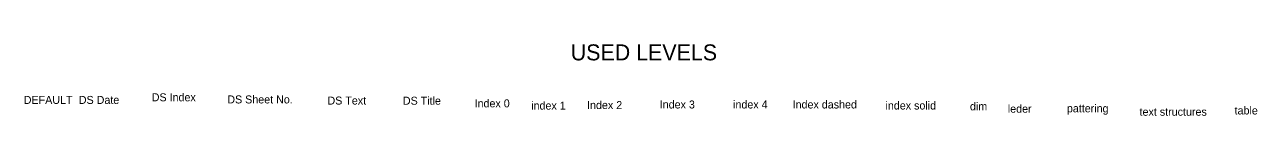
# Model space of a CAD drawing. Extents: x -1.3 to 14.5, y 0 to 8.2.
# Drawn here: x -1.2655 to -1.1115, y -0.0193 to -0.0103 of the extents above; entities that cross this region are included whole.
import ezdxf

# ---------------------------------------------------------------- set-up
doc = ezdxf.new("R2010")
doc.units = 0
for name, color, linetype in [('Default', 7, 'Continuous'), ('Dimension', 7, 'Continuous'), ('DSDate', 7, 'Continuous'), ('DSIndex', 7, 'Continuous'), ('DSSheetNo', 7, 'Continuous'), ('DSText', 7, 'Continuous'), ('DSTitle', 7, 'Continuous'), ('IndexDetail_0', 7, 'Continuous'), ('IndexDetail_1', 7, 'Continuous'), ('IndexDetail_2', 7, 'Continuous'), ('IndexDetail_3', 7, 'Continuous'), ('IndexDetail_4', 7, 'Continuous'), ('IndexDetail_Dashed', 7, 'Continuous'), ('IndexDetail_Solid', 7, 'Continuous'), ('Leader', 7, 'Continuous'), ('Patterning', 7, 'Continuous'), ('Table', 7, 'Continuous'), ('TextStructures', 7, 'Continuous')]:
    doc.layers.add(name, color=color, linetype=linetype)

msp = doc.modelspace()

# ---------------------------------------------------------------- texts
at = {"layer": 'Default'}
for s, height, p in [('USED LEVELS', 0.002, (-1.1973, -0.01233)), ('DEFAULT', 0.001, (-1.26563, -0.01778))]:
    msp.add_text(s, height=height, dxfattribs=at).set_placement(p)
at = {"layer": 'Dimension'}
msp.add_text('dim', height=0.001, dxfattribs=at).set_placement((-1.14743, -0.01858))
at = {"layer": 'DSDate'}
msp.add_text('DS Date', height=0.001, dxfattribs=at).set_placement((-1.25875, -0.01778))
at = {"layer": 'DSIndex'}
msp.add_text('DS Index', height=0.001, dxfattribs=at).set_placement((-1.24964, -0.01745))
at = {"layer": 'DSSheetNo'}
msp.add_text('DS Sheet No.', height=0.001, dxfattribs=at).set_placement((-1.2402, -0.01772))
at = {"layer": 'DSText'}
msp.add_text('DS Text', height=0.001, dxfattribs=at).set_placement((-1.22769, -0.01786))
at = {"layer": 'DSTitle'}
msp.add_text('DS Title', height=0.001, dxfattribs=at).set_placement((-1.21827, -0.01788))
at = {"layer": 'IndexDetail_0'}
msp.add_text('Index 0', height=0.001, dxfattribs=at).set_placement((-1.20931, -0.01821))
at = {"layer": 'IndexDetail_1'}
msp.add_text('index 1', height=0.001, dxfattribs=at).set_placement((-1.20224, -0.01849))
at = {"layer": 'IndexDetail_2'}
msp.add_text('Index 2', height=0.001, dxfattribs=at).set_placement((-1.19526, -0.01842))
at = {"layer": 'IndexDetail_3'}
msp.add_text('Index 3', height=0.001, dxfattribs=at).set_placement((-1.18618, -0.01835))
at = {"layer": 'IndexDetail_4'}
msp.add_text('index 4', height=0.001, dxfattribs=at).set_placement((-1.17702, -0.01835))
at = {"layer": 'IndexDetail_Dashed'}
msp.add_text('Index dashed', height=0.001, dxfattribs=at).set_placement((-1.16958, -0.01835))
at = {"layer": 'IndexDetail_Solid'}
msp.add_text('index solid', height=0.001, dxfattribs=at).set_placement((-1.15798, -0.01848))
at = {"layer": 'Leader'}
msp.add_text('leder', height=0.001, dxfattribs=at).set_placement((-1.1427, -0.01888))
at = {"layer": 'Patterning'}
msp.add_text('pattering', height=0.001, dxfattribs=at).set_placement((-1.13532, -0.01883))
at = {"layer": 'Table'}
msp.add_text('table', height=0.001, dxfattribs=at).set_placement((-1.11437, -0.0191))
at = {"layer": 'TextStructures'}
msp.add_text('text structures', height=0.001, dxfattribs=at).set_placement((-1.12624, -0.01926))

doc.saveas('drawing.dxf')
